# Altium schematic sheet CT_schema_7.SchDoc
size 147 x 119 mm
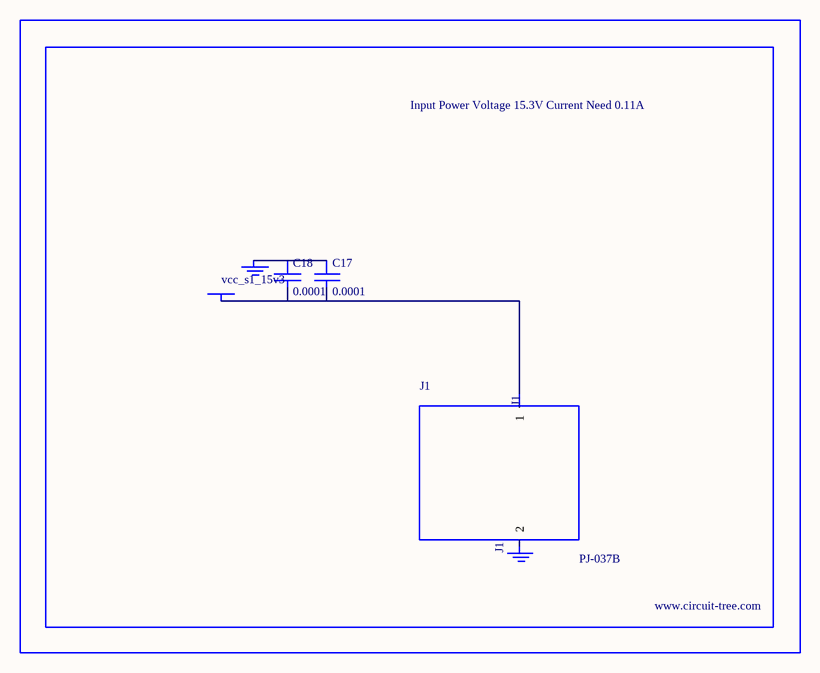
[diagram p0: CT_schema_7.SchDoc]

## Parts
BORDER6  (no value)
C17  0.0001  [EXV-9H]
C18  0.0001  [EXV-9H]
GND_INSTANCE_6_0  (no value)
GND_INSTANCE_6_1  (no value)
J1  PJ-037B  [PJ-037B_PACKAGE]
POWER_INSTANCE_6_0  vcc_s1_15v3

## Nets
NetC17_1: C17.1 C18.1 GND_INSTANCE_6_0.0(GND)
NetC17_2: C17.2 C18.2 J1.1 POWER_INSTANCE_6_0.0(PWR)

Not connected (* = marked no-connect by the designer): GND_INSTANCE_6_1 0(GND); J1 2

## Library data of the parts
BORDER6 = BORDER_PAGE6
C17 C18 = EDK107M035A9HAA
GND_INSTANCE_6_0 GND_INSTANCE_6_1 = GND
POWER_INSTANCE_6_0 = PWR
